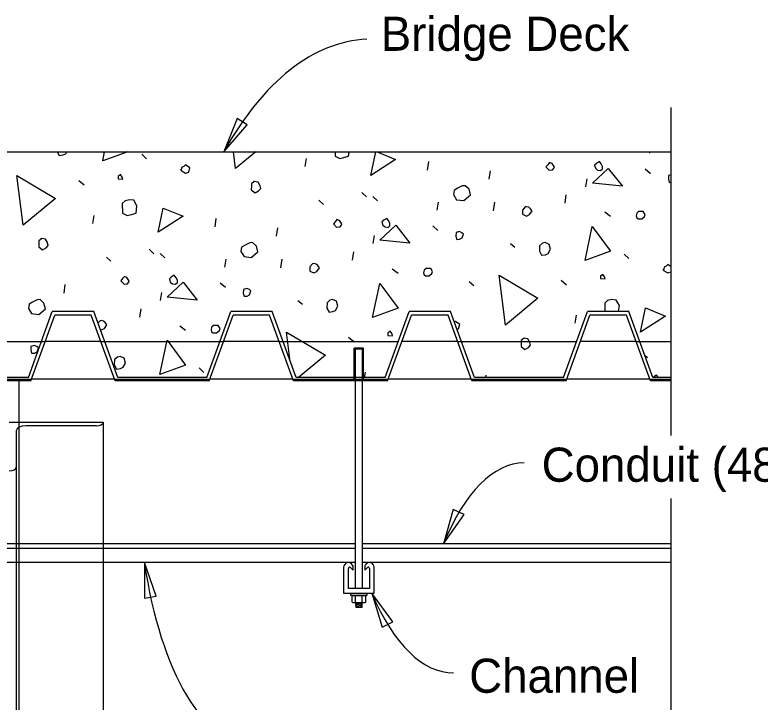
# Model space of a CAD drawing. Extents: x 112544 to 112597.1, y 111084 to 111107.1.
# Drawn here: x 112561.845 to 112565.147, y 111092 to 111095.045 of the extents above; entities that cross this region are included whole.
import ezdxf

# ---------------------------------------------------------------- set-up
doc = ezdxf.new("R2010")
doc.units = 0
for name, color, linetype in [('Dimension', 7, 'Continuous'), ('Lighting', 7, 'Continuous'), ('Lighting_h', 7, 'Continuous'), ('Miscellaneous', 7, 'Continuous'), ('SteelGirder', 7, 'Continuous'), ('SteelGirder_h', 7, 'Continuous'), ('SupstrConc', 7, 'Continuous'), ('TextStructures', 7, 'Continuous')]:
    doc.layers.add(name, color=color, linetype=linetype)

msp = doc.modelspace()

# ---------------------------------------------------------------- linework, layer by layer
at = {"layer": 'Dimension'}
for points in [[(112564.7526, 111093.1822), (112564.7526, 111094.6352)], [(112564.7526, 111086.9751), (112564.7526, 111090.7348), (112564.6751, 111090.7348), (112564.7526, 111090.7686), (112564.8301, 111090.8023), (112564.7526, 111090.8023), (112564.7526, 111092.9028)]]:
    msp.add_lwpolyline(points, dxfattribs=at)
for points in [[(112562.7703, 111094.4391), (112562.8749, 111094.558), (112562.8299, 111094.5859)], [(112563.7439, 111092.7018), (112563.8352, 111092.8313), (112563.7874, 111092.8541)], [(112562.4188, 111092.6185), (112562.4189, 111092.4601), (112562.4711, 111092.469)], [(112563.4264, 111092.4831), (112563.4727, 111092.3316), (112563.52, 111092.3554)]]:
    msp.add_lwpolyline(points, close=True, dxfattribs=at)
for centre, major_axis, ratio, start_param, end_param in [((112563.5154, 111092.5703), (0.1111, -2.3674), 0.464296, 3.141604, 3.781059), ((112564.1094, 111091.879), (0.0076, -1.1813), 0.426092, 3.141637, 3.939024), ((112562.8948, 111092.9892), (0.0076, -1.1813), 0.426092, 5.02876, 6.283138), ((112563.7811, 111093.3109), (0.0076, -1.1813), 0.426092, 5.486066, 6.283138)]:
    msp.add_ellipse(centre, major_axis=major_axis, ratio=ratio, start_param=start_param, end_param=end_param, dxfattribs=at)
at = {"layer": 'Lighting'}
for p, q in [((112563.3538, 111092.7018), (112562.2368, 111092.7018)), ((112564.7526, 111092.7018), (112563.385, 111092.7018)), ((112563.3538, 111092.681), (112562.2368, 111092.681)), ((112564.7526, 111092.681), (112563.385, 111092.681)), ((112563.3538, 111092.6185), (112562.2368, 111092.6185)), ((112563.3017, 111092.5977), (112563.3017, 111092.4831)), ((112563.3314, 111092.5966), (112563.3433, 111092.5847)), ((112563.3433, 111092.6026), (112563.3412, 111092.6069)), ((112563.3433, 111092.5847), (112563.3433, 111092.6026)), ((112564.7526, 111092.6185), (112563.385, 111092.6185)), ((112563.3977, 111092.6069), (112563.3955, 111092.6026)), ((112563.3955, 111092.6026), (112563.3955, 111092.5847)), ((112563.3955, 111092.5847), (112563.4074, 111092.5966)), ((112563.4371, 111092.4831), (112563.4371, 111092.5977)), ((112563.3225, 111092.5039), (112563.3225, 111092.5929)), ((112563.4163, 111092.5929), (112563.4163, 111092.5039)), ((112563.4163, 111092.5039), (112563.3225, 111092.5039)), ((112563.3017, 111092.4831), (112563.4371, 111092.4831))]:
    msp.add_line(p, q, dxfattribs=at)
for centre, radius, start, end in [((112563.3225, 111092.5977), 0.0208, 26.1794, 179.9999), ((112563.3277, 111092.5929), 0.0052, 45, 180), ((112563.4163, 111092.5977), 0.0208, 0.0001, 153.8206), ((112563.4111, 111092.5929), 0.0052, 360, 135)]:
    msp.add_arc(centre, radius, start, end, dxfattribs=at)
at = {"layer": 'Lighting_h'}
for p, q in [((112562.2368, 111092.7018), (112561.6431, 111092.7018)), ((112562.2368, 111092.681), (112561.6431, 111092.681)), ((112562.2368, 111092.6185), (112561.6431, 111092.6185))]:
    msp.add_line(p, q, dxfattribs=at)
at = {"layer": 'Miscellaneous'}
for p, q in [((112562.4077, 111094.4276), (112562.4286, 111094.4073)), ((112564.658, 111094.4327), (112564.6592, 111094.4392)), ((112563.1314, 111094.373), (112563.1375, 111094.4083)), ((112563.6738, 111094.3579), (112563.6793, 111094.3956)), ((112563.9462, 111094.317), (112563.9516, 111094.3547)), ((112564.638, 111094.3626), (112564.6614, 111094.343)), ((112564.3743, 111094.2842), (112564.3804, 111094.3195)), ((112562.1282, 111094.3113), (112562.1516, 111094.2917)), ((112563.382, 111094.259), (112563.403, 111094.2387)), ((112564.2828, 111094.2105), (112564.2882, 111094.2482)), ((112563.1922, 111094.2237), (112563.2125, 111094.2058)), ((112563.4308, 111094.241), (112563.4518, 111094.2208)), ((112563.7163, 111094.1803), (112563.7223, 111094.2156)), ((112563.9655, 111094.1772), (112563.971, 111094.2149)), ((112562.1897, 111094.1207), (112562.1957, 111094.156)), ((112564.4587, 111094.1722), (112564.4844, 111094.1532)), ((112562.7321, 111094.1056), (112562.7375, 111094.1432)), ((112563.0044, 111094.0647), (112563.0099, 111094.1023)), ((112563.6962, 111094.1103), (112563.7196, 111094.0906)), ((112563.4325, 111094.0318), (112563.4386, 111094.0671)), ((112564.0408, 111094.0318), (112564.0604, 111094.0163)), ((112562.4402, 111094.0066), (112562.4612, 111093.9864)), ((112562.489, 111093.9887), (112562.51, 111093.9684)), ((112563.341, 111093.9581), (112563.3464, 111093.9958)), ((112564.5449, 111093.9857), (112564.5658, 111093.9654)), ((112562.2504, 111093.9713), (112562.2707, 111093.9535)), ((112562.7745, 111093.928), (112562.7806, 111093.9633)), ((112563.0238, 111093.9249), (112563.0292, 111093.9626)), ((112563.5169, 111093.9198), (112563.5427, 111093.9009)), ((112562.7544, 111093.8579), (112562.7778, 111093.8383)), ((112563.858, 111093.8637), (112563.8783, 111093.8459)), ((112564.2654, 111093.8694), (112564.2888, 111093.8498)), ((112562.0627, 111093.8123), (112562.0681, 111093.85)), ((112562.4907, 111093.7795), (112562.4968, 111093.8148)), ((112563.099, 111093.7794), (112563.1186, 111093.764)), ((112561.9047, 111093.4391), (112562.0109, 111093.7309)), ((112562.1942, 111093.7309), (112562.0109, 111093.7309)), ((112562.3004, 111093.4391), (112562.1942, 111093.7309)), ((112562.3992, 111093.7058), (112562.4046, 111093.7435)), ((112562.6951, 111093.4391), (112562.8013, 111093.7309)), ((112562.9846, 111093.7309), (112562.8013, 111093.7309)), ((112563.0908, 111093.4391), (112562.9846, 111093.7309)), ((112563.4856, 111093.4391), (112563.5918, 111093.7309)), ((112563.7751, 111093.7309), (112563.5918, 111093.7309)), ((112563.6031, 111093.7333), (112563.6056, 111093.7309)), ((112563.8813, 111093.4391), (112563.7751, 111093.7309)), ((112564.276, 111093.4391), (112564.3822, 111093.7309)), ((112564.5655, 111093.7309), (112564.3822, 111093.7309)), ((112564.6717, 111093.4391), (112564.5655, 111093.7309)), ((112561.9156, 111093.4235), (112562.0218, 111093.7153)), ((112562.1833, 111093.7153), (112562.0218, 111093.7153)), ((112562.2894, 111093.4235), (112562.1833, 111093.7153)), ((112562.706, 111093.4235), (112562.8122, 111093.7153)), ((112562.9737, 111093.7153), (112562.8122, 111093.7153)), ((112563.0799, 111093.4235), (112562.9737, 111093.7153)), ((112563.4965, 111093.4235), (112563.6027, 111093.7153)), ((112563.7641, 111093.7153), (112563.6027, 111093.7153)), ((112563.8703, 111093.4235), (112563.7641, 111093.7153)), ((112564.2869, 111093.4235), (112564.3931, 111093.7153)), ((112564.3269, 111093.6788), (112564.3329, 111093.7141)), ((112564.5546, 111093.7153), (112564.3931, 111093.7153)), ((112564.6608, 111093.4235), (112564.5546, 111093.7153)), ((112562.5751, 111093.6675), (112562.6009, 111093.6485)), ((112563.3237, 111093.617), (112563.347, 111093.5974)), ((112564.6359, 111093.5374), (112564.6472, 111093.5265)), ((112562.6613, 111093.481), (112562.6823, 111093.4607)), ((112563.3942, 111093.4391), (112563.3981, 111093.4617)), ((112561.9156, 111093.4235), (112561.499, 111093.4235)), ((112561.9047, 111093.4391), (112561.5099, 111093.4391)), ((112562.706, 111093.4235), (112562.2894, 111093.4235)), ((112562.6951, 111093.4391), (112562.3004, 111093.4391)), ((112563.4965, 111093.4235), (112563.0799, 111093.4235)), ((112563.4856, 111093.4391), (112563.0908, 111093.4391)), ((112564.2869, 111093.4235), (112563.8703, 111093.4235)), ((112564.276, 111093.4391), (112563.8813, 111093.4391)), ((112563.9315, 111093.4391), (112563.9329, 111093.449)), ((112564.7526, 111093.4235), (112564.6608, 111093.4235)), ((112564.7526, 111093.4391), (112564.6717, 111093.4391))]:
    msp.add_line(p, q, dxfattribs=at)
for points in [[(112562.0323, 111094.4392), (112562.0415, 111094.4226), (112562.059, 111094.4247), (112562.0705, 111094.4304), (112562.0755, 111094.4392)], [(112562.2341, 111094.3992), (112562.2426, 111094.4392)], [(112562.3455, 111094.4392), (112562.2341, 111094.3992)], [(112562.8229, 111094.3654), (112562.8135, 111094.4392)], [(112562.9124, 111094.4392), (112562.8229, 111094.3654)], [(112563.2635, 111094.4392), (112563.2641, 111094.4189), (112563.2849, 111094.409), (112563.2969, 111094.4122), (112563.3235, 111094.4193), (112563.3262, 111094.4392)], [(112563.4214, 111094.3342), (112563.444, 111094.4392)], [(112563.4497, 111094.4392), (112563.5318, 111094.4052), (112563.4214, 111094.3342)], [(112562.5823, 111094.3553), (112562.6007, 111094.3447), (112562.6152, 111094.3486), (112562.6203, 111094.3681), (112562.6013, 111094.3811), (112562.5929, 111094.3737), (112562.5839, 111094.3687), (112562.5823, 111094.3553), (112562.581, 111094.3601)], [(112564.1982, 111094.3716), (112564.2124, 111094.3573), (112564.2275, 111094.3587), (112564.2352, 111094.3686), (112564.2339, 111094.3734), (112564.2252, 111094.3866), (112564.2136, 111094.3912), (112564.2059, 111094.3814), (112564.1982, 111094.3716)], [(112564.4172, 111094.3656), (112564.427, 111094.3578), (112564.4404, 111094.3562), (112564.4488, 111094.3637), (112564.4486, 111094.374), (112564.4429, 111094.3854), (112564.4349, 111094.3962), (112564.4217, 111094.3875), (112564.4133, 111094.38), (112564.4172, 111094.3656)], [(112564.4037, 111094.2998), (112564.4742, 111094.3653), (112564.5368, 111094.2863), (112564.4037, 111094.2998)], [(112561.8811, 111094.1131), (112561.8532, 111094.3333), (112562.0253, 111094.2319), (112561.8811, 111094.1131)], [(112562.3022, 111094.3191), (112562.3234, 111094.317), (112562.3208, 111094.3267), (112562.3128, 111094.3374), (112562.302, 111094.3294), (112562.3022, 111094.3191)], [(112564.7526, 111094.3364), (112564.7416, 111094.3334), (112564.7406, 111094.3176)], [(112564.7406, 111094.3176), (112564.7445, 111094.3031), (112564.7526, 111094.3037)], [(112562.8927, 111094.2884), (112562.8924, 111094.2702), (112562.909, 111094.2565), (112562.9246, 111094.2659), (112562.9348, 111094.2763), (112562.9315, 111094.2884), (112562.9222, 111094.304), (112562.9057, 111094.3074), (112562.8932, 111094.2963), (112562.8927, 111094.2884)], [(112563.7885, 111094.2489), (112563.8022, 111094.2266), (112563.8344, 111094.2223), (112563.8637, 111094.2483), (112563.8572, 111094.2724), (112563.84, 111094.2885), (112563.8272, 111094.2877), (112563.8068, 111094.2771), (112563.7912, 111094.2677), (112563.7885, 111094.2489)], [(112562.321, 111094.2102), (112562.3223, 111094.1666), (112562.3431, 111094.1566), (112562.3552, 111094.1599), (112562.3817, 111094.167), (112562.386, 111094.1992), (112562.3717, 111094.2238), (112562.3528, 111094.2265), (112562.3335, 111094.2213), (112562.321, 111094.2102)], [(112562.4796, 111094.0819), (112562.5026, 111094.189), (112562.59, 111094.1529), (112562.4796, 111094.0819)], [(112564.094, 111094.1806), (112564.0937, 111094.1624), (112564.1115, 111094.1542), (112564.1253, 111094.1605), (112564.1366, 111094.1765), (112564.1285, 111094.1873), (112564.1217, 111094.1932), (112564.1108, 111094.1955), (112564.1059, 111094.1942), (112564.094, 111094.1806)], [(112564.6004, 111094.1455), (112564.6065, 111094.1419), (112564.6223, 111094.141), (112564.6349, 111094.1521), (112564.6377, 111094.1607), (112564.629, 111094.1739), (112564.6084, 111094.1735), (112564.6001, 111094.1661), (112564.5978, 111094.1551), (112564.6004, 111094.1455)], [(112563.2564, 111094.1192), (112563.2706, 111094.1049), (112563.2857, 111094.1064), (112563.2934, 111094.1162), (112563.2921, 111094.121), (112563.2834, 111094.1342), (112563.2718, 111094.1389), (112563.2641, 111094.1291), (112563.2564, 111094.1192)], [(112563.4754, 111094.1132), (112563.4852, 111094.1055), (112563.4986, 111094.1039), (112563.507, 111094.1113), (112563.5068, 111094.1216), (112563.5012, 111094.133), (112563.4931, 111094.1438), (112563.4799, 111094.1351), (112563.4715, 111094.1277), (112563.4754, 111094.1132)], [(112563.462, 111094.0475), (112563.5324, 111094.113), (112563.595, 111094.034), (112563.462, 111094.0475)], [(112563.7988, 111094.0653), (112563.8027, 111094.0508), (112563.8154, 111094.0516), (112563.8269, 111094.0573), (112563.8326, 111094.0743), (112563.8259, 111094.0803), (112563.8143, 111094.0849), (112563.7998, 111094.0811), (112563.7988, 111094.0653)], [(112564.3713, 111093.9573), (112564.4033, 111094.1082), (112564.4846, 111093.998), (112564.3713, 111093.9573)], [(112561.9509, 111094.036), (112561.9506, 111094.0178), (112561.9673, 111094.0041), (112561.9829, 111094.0135), (112561.993, 111094.024), (112561.9898, 111094.0361), (112561.9804, 111094.0517), (112561.964, 111094.055), (112561.9514, 111094.0439), (112561.9509, 111094.036)], [(112562.8467, 111093.9965), (112562.8604, 111093.9743), (112562.8926, 111093.97), (112562.9219, 111093.996), (112562.9154, 111094.0201), (112562.8982, 111094.0362), (112562.8855, 111094.0354), (112562.865, 111094.0247), (112562.8494, 111094.0154), (112562.8467, 111093.9965)], [(112564.1701, 111094.0224), (112564.1687, 111093.9987), (112564.1787, 111093.9807), (112564.1962, 111093.9828), (112564.2077, 111093.9885), (112564.2183, 111094.0068), (112564.2124, 111094.0286), (112564.1947, 111094.0368), (112564.1826, 111094.0335), (112564.1701, 111094.0224)], [(112563.1523, 111093.9283), (112563.152, 111093.9101), (112563.1697, 111093.9019), (112563.1835, 111093.9082), (112563.1948, 111093.9241), (112563.1867, 111093.9349), (112563.18, 111093.9409), (112563.169, 111093.9431), (112563.1642, 111093.9418), (112563.1523, 111093.9283)], [(112563.6586, 111093.8931), (112563.6647, 111093.8896), (112563.6805, 111093.8886), (112563.6931, 111093.8998), (112563.696, 111093.9083), (112563.6873, 111093.9215), (112563.6666, 111093.9212), (112563.6583, 111093.9137), (112563.656, 111093.9028), (112563.6586, 111093.8931)], [(112564.7526, 111093.9296), (112564.7385, 111093.9392), (112564.7301, 111093.9318), (112564.7211, 111093.9268), (112564.7195, 111093.9134), (112564.7182, 111093.9182)], [(112562.3146, 111093.8669), (112562.3288, 111093.8526), (112562.3439, 111093.854), (112562.3517, 111093.8639), (112562.3504, 111093.8687), (112562.3417, 111093.8819), (112562.3301, 111093.8865), (112562.3223, 111093.8767), (112562.3146, 111093.8669)], [(112562.5336, 111093.8609), (112562.5435, 111093.8531), (112562.5568, 111093.8515), (112562.5652, 111093.859), (112562.565, 111093.8693), (112562.5594, 111093.8807), (112562.5513, 111093.8915), (112562.5381, 111093.8828), (112562.5298, 111093.8753), (112562.5336, 111093.8609)], [(112564.0183, 111093.6712), (112563.9904, 111093.8914), (112564.1625, 111093.79), (112564.0183, 111093.6712)], [(112564.4394, 111093.8772), (112564.4606, 111093.8751), (112564.458, 111093.8847), (112564.45, 111093.8955), (112564.4392, 111093.8875), (112564.4394, 111093.8772)], [(112564.7195, 111093.9134), (112564.7379, 111093.9028), (112564.7524, 111093.9067), (112564.7526, 111093.9074)], [(112562.5202, 111093.7951), (112562.5906, 111093.8606), (112562.6532, 111093.7816), (112562.5202, 111093.7951)], [(112563.4295, 111093.7049), (112563.4616, 111093.8558), (112563.5428, 111093.7456), (112563.4295, 111093.7049)], [(112562.8571, 111093.8129), (112562.8609, 111093.7984), (112562.8737, 111093.7993), (112562.8851, 111093.8049), (112562.8909, 111093.822), (112562.8841, 111093.8279), (112562.8725, 111093.8326), (112562.858, 111093.8287), (112562.8571, 111093.8129)], [(112561.9049, 111093.7442), (112561.9186, 111093.722), (112561.9508, 111093.7176), (112561.9801, 111093.7436), (112561.9737, 111093.7678), (112561.9564, 111093.7838), (112561.9437, 111093.783), (112561.9232, 111093.7724), (112561.9076, 111093.763), (112561.9049, 111093.7442)], [(112563.2283, 111093.7701), (112563.2269, 111093.7464), (112563.2369, 111093.7284), (112563.2544, 111093.7305), (112563.2659, 111093.7361), (112563.2765, 111093.7545), (112563.2707, 111093.7762), (112563.2529, 111093.7844), (112563.2409, 111093.7812), (112563.2283, 111093.7701)], [(112564.5197, 111093.7309), (112564.5232, 111093.7573), (112564.5089, 111093.7819), (112564.49, 111093.7846), (112564.4707, 111093.7794), (112564.4582, 111093.7683)], [(112564.4582, 111093.7683), (112564.4593, 111093.7309)], [(112564.6168, 111093.64), (112564.6398, 111093.7471), (112564.7272, 111093.711), (112564.6168, 111093.64)], [(112562.223, 111093.6518), (112562.2279, 111093.6495), (112562.2418, 111093.6558), (112562.253, 111093.6718), (112562.2449, 111093.6826), (112562.2382, 111093.6885), (112562.2272, 111093.6908), (112562.2224, 111093.6895), (112562.2131, 111093.6789)], [(112563.8036, 111093.6524), (112563.8106, 111093.6543), (112563.8157, 111093.6738), (112563.7967, 111093.6868), (112563.7925, 111093.6831)], [(112562.7168, 111093.6408), (112562.723, 111093.6372), (112562.7387, 111093.6363), (112562.7513, 111093.6474), (112562.7542, 111093.656), (112562.7455, 111093.6692), (112562.7249, 111093.6688), (112562.7165, 111093.6614), (112562.7143, 111093.6504), (112562.7168, 111093.6408)], [(112563.0649, 111093.5102), (112563.0486, 111093.6391), (112563.2207, 111093.5377), (112563.1012, 111093.4391)], [(112563.4976, 111093.6248), (112563.5188, 111093.6227), (112563.5163, 111093.6324), (112563.5082, 111093.6432), (112563.4974, 111093.6351), (112563.4976, 111093.6248)], [(112562.4877, 111093.4526), (112562.5198, 111093.6035), (112562.6011, 111093.4933), (112562.4877, 111093.4526)], [(112564.0881, 111093.5941), (112564.0878, 111093.5759), (112564.1045, 111093.5622), (112564.1201, 111093.5716), (112564.1302, 111093.5821), (112564.127, 111093.5942), (112564.1176, 111093.6098), (112564.1012, 111093.6131), (112564.0886, 111093.602), (112564.0881, 111093.5941)], [(112561.9153, 111093.5606), (112561.9192, 111093.5461), (112561.9319, 111093.5469), (112561.9433, 111093.5526), (112561.9491, 111093.5696), (112561.9423, 111093.5756), (112561.9307, 111093.5803), (112561.9162, 111093.5764), (112561.9153, 111093.5606)], [(112562.2865, 111093.5177), (112562.2851, 111093.494), (112562.2951, 111093.476), (112562.3127, 111093.4781), (112562.3241, 111093.4838), (112562.3347, 111093.5021), (112562.3289, 111093.5239), (112562.3112, 111093.5321), (112562.2991, 111093.5288), (112562.2865, 111093.5177)], [(112564.6963, 111093.4391), (112564.6885, 111093.4496), (112564.6753, 111093.4409), (112564.6734, 111093.4391)]]:
    msp.add_lwpolyline(points, dxfattribs=at)
at = {"layer": 'SteelGirder'}
for p, q in [((112562.226, 111093.5979), (112561.9791, 111093.5979)), ((112563.0164, 111093.5979), (112562.7695, 111093.5979)), ((112563.8069, 111093.5979), (112563.5599, 111093.5979)), ((112564.5973, 111093.5979), (112564.3504, 111093.5979)), ((112563.3902, 111093.5693), (112563.3486, 111093.5693)), ((112563.3486, 111093.4235), (112563.3486, 111093.5693)), ((112563.3538, 111092.5039), (112563.3538, 111093.5641)), ((112563.385, 111093.5641), (112563.3538, 111093.5641)), ((112563.385, 111092.5039), (112563.385, 111093.5641)), ((112563.3902, 111093.4235), (112563.3902, 111093.5693)), ((112561.8618, 111093.4312), (112561.8618, 111093.2407)), ((112562.2867, 111093.4312), (112561.9184, 111093.4312)), ((112563.0771, 111093.4312), (112562.7088, 111093.4312)), ((112563.8675, 111093.4312), (112563.4993, 111093.4312)), ((112564.658, 111093.4312), (112564.2897, 111093.4312)), ((112561.8201, 111093.2407), (112562.2368, 111093.2407)), ((112562.2056, 111093.2245), (112561.8931, 111093.2245)), ((112562.2368, 111093.2407), (112562.2368, 111088.3699)), ((112561.8514, 111093.2029), (112561.8514, 111093.0412)), ((112561.8514, 111093.0412), (112561.8514, 111088.1702)), ((112563.3393, 111092.4436), (112563.3393, 111092.472)), ((112563.3393, 111092.472), (112563.3995, 111092.472)), ((112563.3544, 111092.4436), (112563.3544, 111092.472)), ((112563.3844, 111092.4436), (112563.3844, 111092.472)), ((112563.3995, 111092.4436), (112563.3995, 111092.472)), ((112563.3468, 111092.4414), (112563.392, 111092.4414)), ((112563.3538, 111092.4408), (112563.3604, 111092.4414)), ((112563.3538, 111092.4408), (112563.3548, 111092.4414)), ((112563.359, 111092.4386), (112563.3538, 111092.4408)), ((112563.3538, 111092.4356), (112563.359, 111092.4386)), ((112563.3538, 111092.4356), (112563.385, 111092.4383)), ((112563.359, 111092.4334), (112563.3538, 111092.4356)), ((112563.3538, 111092.4305), (112563.359, 111092.4334)), ((112563.3538, 111092.4305), (112563.385, 111092.4331)), ((112563.3797, 111092.4405), (112563.3814, 111092.4414)), ((112563.385, 111092.4383), (112563.3797, 111092.4405)), ((112563.3797, 111092.4353), (112563.385, 111092.4383)), ((112563.385, 111092.4331), (112563.3797, 111092.4353)), ((112563.3797, 111092.4301), (112563.385, 111092.4331)), ((112563.359, 111092.4283), (112563.3538, 111092.4305)), ((112563.3538, 111092.4253), (112563.359, 111092.4283)), ((112563.3538, 111092.4253), (112563.385, 111092.428)), ((112563.359, 111092.4231), (112563.3538, 111092.4253)), ((112563.3556, 111092.4211), (112563.359, 111092.4231)), ((112563.3556, 111092.4211), (112563.3821, 111092.4211)), ((112563.3657, 111092.4211), (112563.385, 111092.4228)), ((112563.385, 111092.428), (112563.3797, 111092.4301)), ((112563.3797, 111092.4249), (112563.385, 111092.428)), ((112563.385, 111092.4228), (112563.3797, 111092.4249)), ((112563.3821, 111092.4211), (112563.385, 111092.4228))]:
    msp.add_line(p, q, dxfattribs=at)
msp.add_lwpolyline([(112563.4047, 111092.4831), (112563.4047, 111092.472), (112563.3341, 111092.472), (112563.3341, 111092.4831)], close=True, dxfattribs=at)
for centre, radius, start, end in [((112563.3468, 111092.4552), 0.0138, 236.9791, 303.0209), ((112563.3694, 111092.4933), 0.0519, 253.1396, 286.8604), ((112563.392, 111092.4552), 0.0138, 236.9791, 303.0209)]:
    msp.add_arc(centre, radius, start, end, dxfattribs=at)
for centre, major_axis in [((112561.8931, 111093.2029), (-0.0417, 0)), ((112562.2056, 111093.2407), (0.0313, 0)), ((112561.8201, 111093.0412), (0.0312, 0))]:
    msp.add_ellipse(centre, major_axis=major_axis, ratio=0.5176, start_param=4.712389, end_param=6.283185, dxfattribs=at)
at = {"layer": 'SteelGirder_h'}
for p, q in [((112561.4355, 111093.5979), (112561.9791, 111093.5979)), ((112562.226, 111093.5979), (112562.7695, 111093.5979)), ((112563.0164, 111093.5979), (112563.5433, 111093.5979)), ((112563.8069, 111093.5979), (112564.3338, 111093.5979)), ((112564.5973, 111093.5979), (112564.7526, 111093.5979)), ((112561.4962, 111093.4312), (112561.9184, 111093.4312)), ((112562.2867, 111093.4312), (112562.7088, 111093.4312)), ((112563.0771, 111093.4312), (112563.1501, 111093.4312)), ((112563.0771, 111093.4312), (112563.4993, 111093.4312)), ((112563.8675, 111093.4312), (112563.9405, 111093.4312)), ((112563.8675, 111093.4312), (112564.2897, 111093.4312)), ((112564.658, 111093.4312), (112564.731, 111093.4312)), ((112564.658, 111093.4312), (112564.7526, 111093.4312)), ((112561.8618, 111093.2407), (112561.8618, 111088.3465))]:
    msp.add_line(p, q, dxfattribs=at)
at = {"layer": 'SupstrConc'}
msp.add_line((112557.7434, 111094.4392), (112564.7526, 111094.4392), dxfattribs=at)

# ---------------------------------------------------------------- texts
at = {"layer": 'TextStructures'}
for s, p in [('Bridge Deck', (112563.4661, 111094.8861)), ('Conduit (480V)', (112564.179, 111092.9766)), ('Channel', (112563.8579, 111092.0415))]:
    msp.add_text(s, height=0.1512, dxfattribs=at).set_placement(p)

doc.saveas('drawing.dxf')
